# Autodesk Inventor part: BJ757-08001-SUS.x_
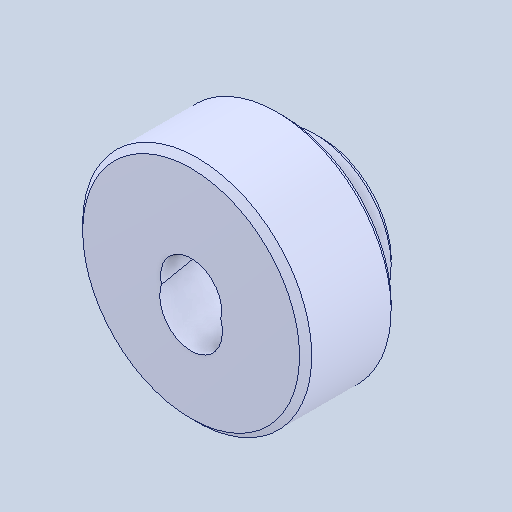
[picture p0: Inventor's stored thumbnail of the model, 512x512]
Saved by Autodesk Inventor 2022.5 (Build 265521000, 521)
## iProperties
Created: 2024-05
Part Number: BJ757-08001-SUS.x_
Material: 一般
Document SubType Name: Modeling
Designer: ImaoCorp
Density: 1 g/cm^3
Appearance: 既定
Author: ImaoCorp
Sending System: SOLIDWORKS 2022-2022290
MC: AMD64
MC_MODEL: Intel64 Family 6 Model 60 Stepping 3, GenuineIntel
OS: Windows_NT
FRU: Parasolid Version 33.1, build 260,  4-25-2022
FORMAT: text
GUISE: transmit
KEY: FILEBJ757-08001-SUS.x_t
DATE: Tue May 21 08:47:09 2024
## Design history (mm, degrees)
feature "Base1"
node "ソリッド1"
